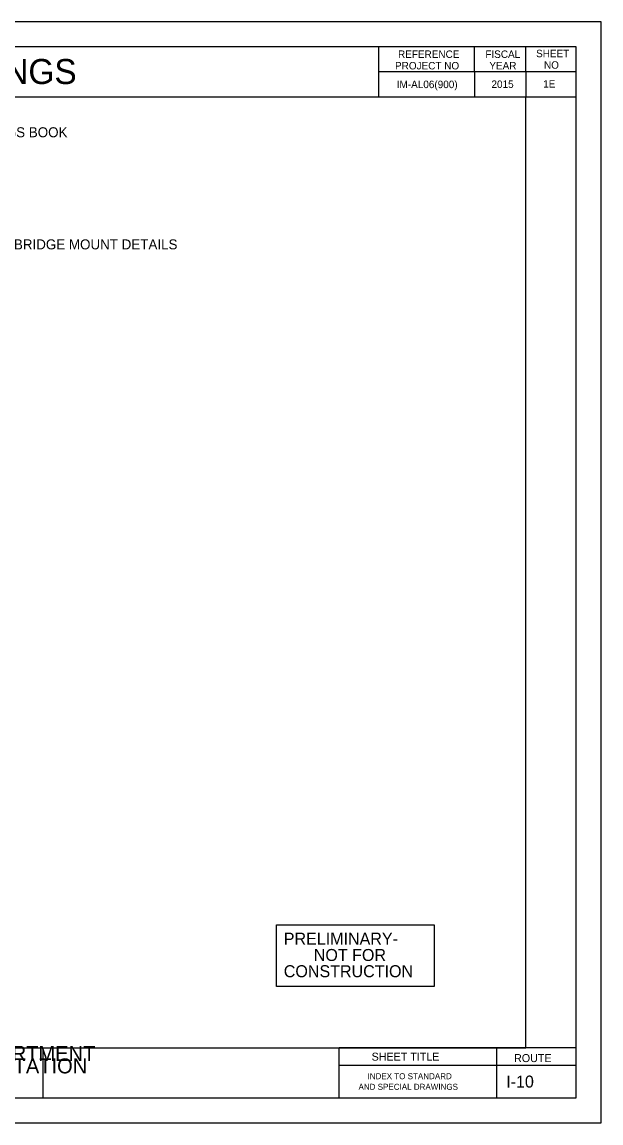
# Model space of a CAD drawing. Extents: x -12822 to 16384, y -6351 to 1913.
# Drawn here: x 271 to 850, y -4850 to -3750 of the extents above; entities that cross this region are included whole.
import ezdxf

# ---------------------------------------------------------------- set-up
doc = ezdxf.new("R2010")
doc.units = 0
for name, color, linetype in [('1', 7, 'Continuous'), ('ANNO-SHT', 7, 'Continuous'), ('ANNO-TXT', 7, 'Continuous'), ('Level 10', 7, 'Continuous'), ('Level 6', 7, 'Continuous'), ('Level 62', 7, 'Continuous'), ('SHT-BDR', 7, 'Continuous'), ('SHT-BNDRY', 7, 'Continuous')]:
    doc.layers.add(name, color=color, linetype=linetype)

msp = doc.modelspace()

# ---------------------------------------------------------------- linework, layer by layer
at = {"layer": '1'}
msp.add_lwpolyline([(525.5, -4652.3), (683.1, -4652.3), (683.1, -4714.1), (525.5, -4714.1)], close=True, dxfattribs=at)
at = {"layer": 'ANNO-TXT'}
for p, q in [((588.3, -4792.7), (745.9, -4792.7)), ((745.9, -4792.7), (825, -4792.7))]:
    msp.add_line(p, q, dxfattribs=at)
at = {"layer": 'Level 6'}
for p, q in [((627.7, -3775.3), (627.7, -3825.3)), ((723.5, -3800.3), (723.5, -3775.3)), ((775, -3799.7), (775, -3775.3)), ((825, -3800), (627.7, -3800)), ((723.5, -3800.3), (723.5, -3825.3)), ((775, -3799.7), (775, -3825.3)), ((825, -3825.3), (633.7, -3825.3)), ((825, -4775.3), (588.3, -4775.3))]:
    msp.add_line(p, q, dxfattribs=at)
at = {"layer": 'Level 62'}
msp.add_lwpolyline([(-850, -4850.3), (850, -4850.3), (850, -3750.3), (-850, -3750.3)], close=True, dxfattribs=at)
at = {"layer": 'SHT-BDR'}
msp.add_lwpolyline([(-725, -4775.3), (775, -4775.3), (775, -3825.3), (-725, -3825.3)], close=True, dxfattribs=at)
at = {"layer": 'SHT-BNDRY'}
for p, q in [((292.3, -4825.3), (292.3, -4775.3)), ((588.3, -4825.3), (588.3, -4775.3)), ((745.9, -4825.3), (745.9, -4775.3))]:
    msp.add_line(p, q, dxfattribs=at)
msp.add_lwpolyline([(-787.5, -4825.3), (825, -4825.3), (825, -3775.3), (-787.5, -3775.3)], close=True, dxfattribs=at)

# ---------------------------------------------------------------- texts
at = {"layer": '1'}
for s, p in [('PRELIMINARY-', (532.9, -4672.2)), ('NOT FOR', (562.9, -4688.5)), ('CONSTRUCTION', (532.9, -4704.7))]:
    msp.add_text(s, height=12, dxfattribs=at).set_placement(p)
at = {"layer": 'ANNO-SHT'}
for s, height, p in [('INDEX TO STANDARD AND SPECIAL DRAWINGS', 24.997, (-448.6, -3812.3)), ('IM-AL06(900)', 7.449, (645.8, -3816.4)), ('2015', 7.45, (740.5, -3816.2)), (' 1E ', 7.45, (789.4, -3815.9)), ('INDEX TO STANDARD', 6, (616.6, -4806.6)), ('  I-10  ', 12, (746.3, -4815)), ('AND SPECIAL DRAWINGS', 6, (607.6, -4817.2))]:
    msp.add_text(s, height=height, dxfattribs=at).set_placement(p)
at = {"layer": 'ANNO-TXT'}
for s, p in [('ALABAMA DEPARTMENT', (106, -4788.3)), ('OF TRANSPORTATION', (118, -4800.8))]:
    msp.add_text(s, height=15, rotation=360, dxfattribs=at).set_placement(p)
for s, p in [('SHEET TITLE', (620.7, -4788.1)), ('ROUTE', (763.1, -4789.5))]:
    msp.add_text(s, height=8, dxfattribs=at).set_placement(p)
at = {"layer": 'Level 10'}
for s, p in [('ALABAMA DEPARTMENT OF TRANSPORTATION SPECIAL AND STANDARD HIGHWAY DRAWINGS BOOK', (-348.3, -3865.5)), ('DETAILS SHOWING CONDUIT RUNS ON CONCRETE STRUCTURES AND SEGMENTED REFLECTOR LUMINAIRE UNDER BRIDGE MOUNT DETAILS', (-502.1, -3977.5))]:
    msp.add_text(s, height=10, dxfattribs=at).set_placement(p)
at = {"layer": 'Level 6'}
for s, p in [('REFERENCE', (647.1, -3786.2)), ('FISCAL', (734.4, -3786.2)), ('SHEET', (785.1, -3785.5)), ('PROJECT NO', (644.1, -3797.7)), ('YEAR', (738.4, -3797.7)), ('NO', (793, -3797))]:
    msp.add_text(s, height=7.44, dxfattribs=at).set_placement(p)

doc.saveas('drawing.dxf')
